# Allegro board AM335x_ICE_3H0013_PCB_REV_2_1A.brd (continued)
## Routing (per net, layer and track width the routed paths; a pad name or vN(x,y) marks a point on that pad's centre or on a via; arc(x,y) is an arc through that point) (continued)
DDR_D13: length 24.9
  TOP w0.121: v1(44.97,46.05) U14.L3 ; U15.A2 v1(59.7,51.02)
  LYR4 w0.127: v1(59.7,51.02) 59.31,51.41 55.82,51.41 55.71,51.3 55.71,50.76 55.6,50.65 55.44,50.65 55.33,50.76 55.33,51.3 55.22,51.41 55.06,51.41 54.95,51.3 54.95,50.76 54.84,50.65 54.68,50.65 54.57,50.76 54.57,51.3 54.46,51.41 54.3,51.41 54.19,51.3 54.19,50.76 54.08,50.65 53.92,50.65 53.81,50.76 53.81,51.3 53.7,51.41 53.43,51.41 53.2,51.18 53.2,50.73 53.05,50.58 51.79,50.58 51.55,50.82 51.55,51.16 51.3,51.41 50.84,51.41 50.59,51.16 50.59,49.85 50.27,49.53 48.25,49.53 47.65,48.93 47.65,47.77 47.12,47.24 45.61,47.24 45.38,47.01 45.38,46.46 v1(44.97,46.05)
DDR_D14: length 25.1
  TOP w0.121: U14.L4 v1(44.17,46.05) ; v1(62.99,50.8) 63.35,50.45 U15.A7
  LYR4 w0.127: v1(62.99,50.8) 61.62,52.17 49.58,52.17 46.25,48.84 44.81,48.84 44.56,48.6 44.56,48.29 44.32,48.04 44.01,48.04 43.78,47.81 43.78,46.44 v1(44.17,46.05)
DDR_D15: length 25.1
  TOP w0.121: U14.M1 v1(46.57,46.85) ; U15.B8 v1(64.9,49.25)
  LYR4 w0.127: v1(64.9,49.25) 64.9,50.6 64.52,50.98 63.92,50.98 63.64,50.7 63.64,50.48 63.36,50.21 62.77,50.21 62.36,50.62 60.07,50.62 59.85,50.41 58.92,50.41 58.34,50.98 56.56,50.98 56.39,50.81 56.39,50.33 56.27,50.21 55.35,50.21 55.35,50.2 51.19,50.2 51,50.01 51,49.27 50.84,49.11 48.35,49.11 48,48.76 48,47.4 47.45,46.85 v1(46.57,46.85)
DDR_DQM0: length 24.8
  TOP w0.121: U14.M2 v1(45.77,46.85) ; U15.E7 v1(63.06,47.25)
  LYR3 w0.127: v1(63.06,47.25) 63.06,46.58 62.6,46.11 62.07,46.11 61.57,45.61 61.57,45.6 61.34,45.37 61.02,45.37 60.78,45.6 60.78,46.07 59.6,47.26 59.14,47.26 58.91,47.49 58.91,47.94 58.41,48.44 58.41,48.91 58.18,49.14 57.8,49.14 57.62,48.96 57.62,48.41 57.52,48.31 50.62,48.31 50.16,48.77 47.64,48.77 46.91,48.04 45.61,48.04 45.38,47.81 45.38,47.32 45.77,46.93 v1(45.77,46.85)
DDR_DQM1: length 25
  TOP w0.121: v1(61.06,48.32) 60.78,48.05 U15.D3 ; U14.J2 45.77,44.45 46.4,44.45 46.86,44.9 v1(47.22,44.9)
  LYR4 w0.127: v1(61.06,48.32) 60.87,48.14 59.12,48.14 58.52,47.54 57.36,47.54 57.26,47.65 56.06,47.65 55.95,47.53 55.95,47.28 55.84,47.17 55.68,47.17 55.57,47.28 55.57,47.53 55.46,47.65 55.3,47.65 55.19,47.53 55.19,47.28 55.07,47.17 54.92,47.17 54.8,47.28 54.8,47.53 54.69,47.65 54.54,47.65 54.41,47.52 54.41,46.83 54.3,46.71 54.15,46.71 54.03,46.83 54.03,47.54 53.93,47.65 53.77,47.65 53.65,47.52 53.65,46.83 53.54,46.71 53.38,46.71 53.27,46.83 53.27,47.54 53.17,47.65 53.01,47.65 52.89,47.52 52.89,46.83 52.78,46.71 52.62,46.71 52.52,46.82 52.52,47.53 52.41,47.65 51.93,47.65 51.7,47.42 51.7,46.33 51.44,46.07 49.32,46.07 48.15,44.9 v1(47.22,44.9)
DDR_DQS0: length 25
  TOP w0.102: U14.P1 v1(46.57,48.45) ; v1(61.18,46.36) 60.8,45.98 60.57,45.98 60.5,46.05 U15.F3
  LYR3 w0.102: v1(61.18,46.36) 61.26,46.43 61.26,47.12 61.08,47.3 60.96,47.3 60.57,46.91 60.41,46.91 60.29,47.04 60.29,47.18 60.68,47.57 60.68,47.7 59.99,48.39 59.2,48.39 58.62,48.97 58.62,49.47 58.44,49.65 57.67,49.65 56.83,48.8 56.19,48.8 55.89,49.1 55.89,49.6 55.79,49.71 55.49,49.71 55.37,49.59 55.37,49.09 55.09,48.8 54.59,48.8 54.29,49.1 54.29,49.53 54.17,49.65 53.94,49.65 53.83,49.53 53.83,49.1 53.53,48.8 53.11,48.8 52.81,49.1 52.81,49.53 52.69,49.65 52.52,49.65 52.4,49.53 52.4,49.1 52.11,48.8 50.82,48.8 50.36,49.27 46.9,49.27 46.42,48.8 46.42,48.6 v1(46.57,48.45)
DDR_DQS1: length 25
  TOP w0.102: U15.C7 63.7,49.18 63.55,49.33 63.2,49.33 63.06,49.2 v1(63.06,48.85)
  TOP w0.121: U14.L1 v1(46.57,46.05)
  LYR4 w0.102: v1(46.57,46.05) 47.94,46.05 48.74,46.85 48.74,48.08 48.89,48.24 51.15,48.24 51.43,48.52 51.81,48.9 51.81,49.25 51.97,49.4 52.52,49.4 52.65,49.27 52.65,48.86 52.94,48.57 53.54,48.57 53.82,48.85 53.82,49.31 53.91,49.4 54.31,49.4 54.4,49.31 54.4,48.91 54.68,48.63 55.3,48.63 55.58,48.91 55.58,49.28 55.68,49.38 55.95,49.38 56.08,49.38 56.16,49.29 56.16,48.92 56.44,48.63 57,48.63 57.31,48.94 57.31,49.46 57.48,49.63 59.14,49.63 59.15,49.63 60.44,49.63 60.84,50.03 61.5,50.03 62.27,49.27 62.64,49.27 v1(63.06,48.85)
DDR_DQSN0: length 25
  TOP w0.102: U15.G3 60.53,45.67 61.08,45.67 v1(61.18,45.77) ; U14.P2 v1(45.77,48.45)
  LYR3 w0.102: v1(45.77,48.45) 46.02,48.7 46.02,48.82 46.77,49.58 50.48,49.58 50.95,49.11 51.98,49.11 52.1,49.23 52.1,49.66 52.4,49.95 52.82,49.95 53.11,49.66 53.11,49.23 53.23,49.11 53.4,49.11 53.52,49.23 53.52,49.66 53.82,49.95 54.3,49.95 54.59,49.66 54.59,49.23 54.71,49.11 54.96,49.11 55.07,49.22 55.07,49.71 55.37,50.01 55.91,50.01 56.2,49.72 56.2,49.23 56.32,49.11 56.7,49.11 57.54,49.95 58.57,49.95 58.93,49.59 58.93,49.41 58.92,49.41 58.92,49.09 59.32,48.69 60.12,48.69 61.56,47.25 61.56,46.15 v1(61.18,45.77)
DDR_DQSN1: length 25
  TOP w0.102: U15.B7 63.69,49.64 62.43,49.64 v1(62.42,49.65) ; U14.L2 v1(45.77,46.05)
  LYR4 w0.102: v1(45.77,46.05) 46.15,46.43 46.73,46.43 46.81,46.35 47.81,46.35 48.44,46.98 48.44,48.21 48.77,48.54 51.02,48.54 51.31,48.83 51.51,49.03 51.51,49.37 51.84,49.71 52.65,49.71 52.96,49.4 52.96,48.99 53.07,48.88 53.41,48.88 53.51,48.98 53.51,49.44 53.79,49.71 54.44,49.71 54.71,49.44 54.71,49.04 54.8,48.94 55.17,48.94 55.27,49.04 55.27,49.41 55.55,49.68 55.82,49.68 56.2,49.68 56.47,49.42 56.47,49.17 56.47,49.04 56.57,48.94 56.88,48.94 57.01,49.07 57.01,49.59 57.36,49.94 59.27,49.94 60.31,49.94 60.71,50.34 61.63,50.34 62.2,49.76 62.31,49.76 v1(62.42,49.65)
DDR_ODT: length 32.2
  TOP w0.121: U15.K1 58.13,43.25 v1(58.09,43.29) ; v1(46.57,42.05) 46.83,41.79 47.22,41.79 47.46,42.04 47.46,42.25 47.26,42.45 U14.G1
  LYR4 w0.127: v1(46.57,42.05) 46.61,42.09 47.16,42.09 47.28,41.97 47.28,41.58 47.39,41.47 47.55,41.47 47.66,41.58 47.66,41.99 47.76,42.09 47.92,42.09 48.04,41.97 48.04,41.58 48.15,41.47 48.31,41.47 48.42,41.58 48.42,41.99 48.52,42.09 50.19,42.09 50.49,42.39 52.21,42.39 52.27,42.39 52.35,42.31 52.35,41.88 52.49,41.75 52.68,41.75 52.8,41.86 52.8,42.84 52.91,42.96 53.06,42.96 53.15,42.87 53.15,42.56 53.24,42.47 53.43,42.47 53.53,42.57 53.53,42.99 53.64,43.1 53.98,43.1 54.11,43.24 54.11,43.64 54.23,43.75 54.38,43.75 54.51,43.63 54.51,43.08 54.61,42.98 54.76,42.98 54.89,43.11 54.89,43.65 54.99,43.75 55.15,43.75 55.27,43.63 55.27,43.07 55.36,42.98 55.55,42.98 55.65,43.08 55.65,43.65 55.75,43.75 55.91,43.75 56.03,43.63 56.03,43.07 56.11,42.99 56.33,42.99 56.41,43.08 56.41,43.65 56.51,43.75 56.67,43.75 56.79,43.63 56.79,43.08 56.88,42.99 57.28,42.99 57.58,43.29 v1(58.09,43.29)
  BOTTOM w0.121: v1(58.09,43.29) 58.25,43.13 58.3,43.13 58.75,42.68 58.75,38.96 58.19,38.41 RP3.2
DDR_RASN: length 31.7
  TOP w0.121: U14.G4 v1(44.17,42.05) ; U15.J3 61.43,44.05 v1(61.52,44.15)
  LYR4 w0.127: v1(44.17,42.05) 43.78,42.44 43.78,44.41 44.01,44.64 44.3,44.64 44.56,44.38 44.56,43.5 44.81,43.26 45.13,43.26 45.49,43.61 49.34,43.61 49.86,44.14 52.96,44.14 53.73,44.92 57.23,44.92 57.37,45.06 59.04,45.06 59.33,45.35 60.5,45.35 60.65,45.19 60.65,44.69 60.65,44.68 60.65,44.54 60.78,44.41 61.26,44.41 v1(61.52,44.15)
  BOTTOM w0.121: v1(61.52,44.15) 61.42,44.05 59.08,44.05 58.04,45.09 55.83,45.09 55.32,44.58
DDR_RESETN: length 33.8
  TOP w0.121: U15.T2 v1(59.3,38.05) 53.42,38.05 R59.2 ; U14.G2 v1(45.77,42.05)
  LYR3 w0.127: v1(59.3,38.05) 58.93,38.42 58.4,38.42 57.83,37.84 56.83,37.84 55.18,39.49 54.7,39.49 54.59,39.6 54.59,40.12 54.48,40.23 54.32,40.23 54.21,40.12 54.21,39.6 54.1,39.49 53.94,39.49 53.83,39.6 53.83,40.12 53.72,40.23 53.56,40.23 53.45,40.12 53.45,39.6 53.34,39.49 53.18,39.49 53.07,39.6 53.07,40.12 52.95,40.23 52.8,40.23 52.69,40.12 52.69,39.6 52.57,39.49 52.42,39.49 52.3,39.6 52.3,40.12 52.19,40.23 52.03,40.23 51.92,40.12 51.92,39.6 51.81,39.49 51.65,39.49 51.54,39.6 51.54,40.12 51.43,40.23 51.27,40.23 51.16,40.12 51.16,39.6 51.05,39.49 50.89,39.49 50.78,39.6 50.78,40.12 50.67,40.23 50.51,40.23 50.4,40.12 50.4,39.6 50.29,39.49 50.13,39.49 50.02,39.6 50.02,40.12 49.91,40.23 49.75,40.23 49.64,40.12 49.64,39.6 49.53,39.49 49.13,39.49 49.02,39.6 49.02,40.16 48.91,40.27 48.71,40.27 48.43,39.99 47.97,39.99 47.92,40.04 46.42,40.04 46.18,40.29 46.18,40.6 45.93,40.84 45.62,40.84 45.38,41.09 45.38,41.41 45.61,41.64 45.61,41.64 45.77,41.8 v1(45.77,42.05)
DDR_VREF: length 43.2
  TOP w0.254: U15.M8 v1(64.9,41.25)
  TOP w0.305: U14.J4 v1(44.17,43.65)
  TOP w0.381: U15.H1 57.89,44.85 v1(56.52,46.23) 52.83,46.23 TP21.1
  BOTTOM w0.254: U29.6 67.33,36.94 67.18,37.08 C188.1
  BOTTOM w0.381: C188.1 67.18,39.37 67.69,39.88 67.69,40.77 67.18,41.27 66.67,41.27
  BOTTOM w0.508: 66.67,41.27 64.93,41.27 v1(64.9,41.25) 64.75,41.4 64.75,41.43 C167.1 64.27,42.2 64.03,42.44 64.03,44.7 62.79,45.94 62.42,45.94 61.42,46.94 58.93,46.94 58.56,47.31 57.2,47.31 56.52,46.63 v1(56.52,46.23) 53.98,46.23 51.31,43.56 C159.1 46.61,44.32 44.7,44.32 44.17,43.79 v1(44.17,43.65)
DDR_VTP: length 4.7
  TOP w0.121: v1(44.97,43.65) U14.J3
  BOTTOM w0.121: v1(44.97,43.65) 45.36,43.26 45.36,41.91 45.61,41.66 47.11,41.66 R185.2
DDR_VTT_EN: length 79.7
  TOP w0.121: v1(33.77,41.25) U14.F16 ; 70.48,32.64 70.13,32.99 v1(69.85,32.99) 69.23,32.99 R62.2 68.75,33.47 68.75,34.31 68.79,34.35 68.79,34.74 68.75,34.78 68.75,36.41 v1(68.07,37.08)
  LYR3 w0.127: v1(29.35,26.12) 29.38,26.12 30.77,24.73 37.72,24.73 37.92,24.53 42.68,24.53 44.93,22.29 53.98,22.29 55.12,21.15 v1(55.12,20.95) ; v1(33.77,41.25) 33.6,41.08 33.52,41.08 32.07,39.64 30.19,39.64 29.21,38.66 v1(29.21,38.25)
  LYR4 w0.127: v1(29.35,26.12) 29.33,26.13 29.33,29.72 29.11,29.94 29.11,31.34 28.53,31.92 28.53,32.52 29.01,32.99 29.01,37.81 29.21,38.01 v1(29.21,38.25) ; v1(69.85,32.99) 69.85,30.7 67.83,28.69 64.03,28.69 63.63,28.28 60,28.28 58.62,26.9 55.27,26.9 54.32,25.95 54.32,23.41 55.12,22.61 v1(55.12,20.95)
  BOTTOM w0.121: U29.7 67.83,36.84 v1(68.07,37.08)
DDR_WEN: length 31.2
  TOP w0.121: U15.L3 61.54,42.45 62.36,41.62 v1(62.36,41.6) ; U14.B2 v1(45.77,38.05)
  LYR4 w0.127: v1(45.77,38.05) 46.28,37.54 46.29,37.54 46.82,37.01 50.2,37.01 50.57,37.38 53.62,37.38 53.69,37.31 58.01,37.31 59.14,38.44 59.47,38.44 59.71,38.2 61.06,38.2 61.18,38.09 61.5,38.09 61.98,38.56 61.98,40.32 62.24,40.58 62.24,40.9 62.54,41.2 63.13,41.2 63.29,41.36 63.29,41.64 63.16,41.77 62.53,41.77 v1(62.36,41.6)
  BOTTOM w0.121: v1(62.36,41.6) 62.25,41.48 62.25,40.62 61.99,40.37 61.99,39.53 62.34,39.18 62.34,37.6 62.76,37.18 RP2.2
DRAIN0: length 80.3
  TOP w0.121: J14.19 74.44,27.16 74.44,51.47 73.43,52.47 v1(73.43,55.81) ; D15.1 v1(77.35,81.57)
  LYR3 w0.127: v1(77.35,81.57) 76.77,80.99 76.77,77.24 77.57,76.44 77.57,60.52 73.41,56.36 73.41,55.84 v1(73.43,55.81)
  LYR4 w0.127: J14.19 74.87,24.83 71.41,24.83 68.99,22.42 60.4,22.42 v1(59.07,21.08)
  BOTTOM w0.121: U31.3 58.55,21.57 59.04,21.08 v1(59.07,21.08)
DRAIN1: length 83.3
  TOP w0.121: J14.20 71.82,27.24 71.82,32.47 71.7,32.58 71.7,34.47 71.18,34.99 71.18,38.03 69.26,39.95 69.26,51.99 69.85,52.58 v1(69.85,53.09) ; D14.1 v1(74.93,81.57)
  LYR3 w0.127: v1(74.93,81.57) 75.68,80.83 75.68,77.1 77.06,75.72 77.06,61.43 72.87,57.24 72.6,57.24 72.17,56.82 72.17,53.55 71.2,52.58 70.36,52.58 v1(69.85,53.09)
  LYR4 w0.127: J14.20 73.24,25.74 71.7,25.74 68.73,22.77 58.25,22.77 v1(57.28,23.75)
  BOTTOM w0.121: U31.4 v1(57.28,23.75)
DRAIN2: length 87.2
  TOP w0.121: D12.1 v1(72.52,81.57) ; v1(73.91,52.58) 74.68,51.81 74.68,29.59 75.82,28.46 J14.21
  LYR3 w0.127: v1(73.91,52.58) 72.43,54.06 72.43,56.71 72.7,56.98 72.97,56.98 77.32,61.33 77.32,76.33 75.93,77.72 75.93,82 75.02,82.91 73.86,82.91 v1(72.52,81.57)
  LYR4 w0.127: J14.21 74.42,26.92 72.49,26.92 68.59,23.03 58.64,23.03 57.49,24.17 56.43,24.17 v1(56.01,23.75)
  BOTTOM w0.121: U31.5 v1(56.01,23.75)
DRAIN3: length 82.5
  TOP w0.121: D10.1 v1(70.11,81.57) ; J14.22 72.06,29.54 72.06,32.57 71.95,32.69 71.95,34.73 71.43,35.25 71.43,52.78 v1(71.12,53.09)
  LYR3 w0.127: v1(70.11,81.57) 71.1,80.57 71.1,80.13 73.27,77.97 73.27,77.06 75.12,75.21 75.12,62.55 72.86,60.29 71.67,60.29 71.41,60.03 71.41,58.67 70.83,58.09 70.83,53.38 v1(71.12,53.09)
  LYR4 w0.127: J14.22 71.51,26.56 70.27,26.56 67.68,23.96 62.54,23.96 61.91,23.33 59.15,23.33 58.05,24.42 55.41,24.42 v1(54.74,23.75)
  BOTTOM w0.121: U31.6 v1(54.74,23.75)
DRAIN4: length 74.1
  TOP w0.121: J14.23 77.25,32.29 77.25,52.23 77.72,52.7 77.72,76.87 v1(77.35,77.25) D9.1
  LYR4 w0.127: v1(54.74,25.78) 55.68,24.84 58.27,24.84 58.81,24.3 65.54,24.3 66.7,25.46 68.63,25.46 72.51,29.34 74.3,29.34 J14.23
  BOTTOM w0.121: U31.11 v1(54.74,25.78)
DRAIN5: length 73.5
  TOP w0.121: v1(71.25,53.85) 71.68,53.42 71.68,35.51 72.2,34.99 72.2,32.99 72.4,32.79 72.4,31.74 J14.24 ; D8.1 v1(74.93,77.25)
  LYR3 w0.127: v1(74.93,77.25) 76.45,75.74 76.45,74.11 76.07,73.73 76.07,64.01 76.29,63.79 76.29,61.02 76.01,60.74 75.74,60.74 71.89,56.89 71.89,54.49 v1(71.25,53.85)
  LYR4 w0.127: v1(56.01,25.78) 56.68,25.11 59.74,25.11 61.05,26.42 61.05,26.79 61.78,27.52 63.05,27.52 63.76,26.8 65.02,26.8 65.4,27.18 69.6,27.18 J14.24
  BOTTOM w0.121: U31.12 v1(56.01,25.78)
DRAIN6: length 73.6
  TOP w0.121: J14.25 76.87,34.45 76.87,53.05 v1(76.77,53.15) 76.78,53.15 77.48,53.85 77.48,75.69 76.96,76.2 73.55,76.2 73.15,76.6 73.15,76.62 v1(72.52,77.25) D7.1
  LYR4 w0.127: J14.25 74.42,32 73.07,32 72.33,31.26 72.33,31.06 68.83,27.56 65.15,27.56 64.9,27.31 63.63,27.31 63.16,27.77 61.18,27.77 58.76,25.36 57.73,25.36 57.32,25.78 v1(57.28,25.78)
  BOTTOM w0.121: U31.13 v1(57.28,25.78)
DRAIN7: length 83
  TOP w0.121: D6.1 v1(70.11,77.25) ; v1(71.37,54.99) 72,54.36 72,35.69 72.44,35.25 72.44,34.24 J14.26
  LYR3 w0.127: v1(71.37,54.99) 71.37,58.28 71.67,58.57 71.67,59.86 71.84,60.03 72.96,60.03 75.37,62.44 75.37,73.85 75.94,74.42 75.94,75.71 75.46,76.2 75.18,76.2 74.2,77.18 74.2,78.9 70.19,82.91 69.8,82.91 69.53,82.63 69.53,81.55 70.47,80.61 70.47,77.61 v1(70.11,77.25)
  LYR4 w0.127: v1(58.55,25.78) 60.79,28.03 63.73,28.03 64.14,28.43 69.34,28.43 72.07,31.17 72.07,32.19 J14.26
  BOTTOM w0.121: U31.14 v1(58.55,25.78)
EMU2_GPIO0_19: length 118.1
  TOP w0.121: U14.A15 34.59,37.27 34.59,35.87 34.24,35.53 34.24,33.69 34.34,33.59 34.34,33.45 34.53,33.26 34.53,31.88 v1(35.62,30.8) ; v1(71.12,62.43) 73.16,64.47 R35.2
  LYR3 w0.127: v1(71.12,62.43) 71.75,63.06 71.75,65.65 72.39,66.29 72.39,67.65 72.27,67.77 72.27,70.15 72.27,70.15 72.27,73.67 71.6,74.33 70,74.33 69.13,75.2 69.13,75.48 67.56,77.05 67.56,84.2 67.02,84.75 67.02,90.49 v1(68.74,92.21)
  LYR4 w0.127: v1(35.62,30.8) 36.51,30.8 37.08,30.23 45.3,30.23 46.01,29.52 52.64,29.52 52.87,29.29 59.63,29.29 59.87,29.53 60.47,29.53 60.49,29.5 65.07,29.5 65.34,29.78 65.34,29.95 68.96,33.57 69.41,33.57 70.37,34.52 70.37,38.65 70.7,38.99 70.7,55.12 71.5,55.92 71.5,61.47 71.12,61.85 v1(71.12,62.43)
  BOTTOM w0.121: v1(68.74,92.21) 70.37,92.21 70.64,92.49 R106.2 72.3,93.23 72.81,92.72 Q2.2
EMU2R: length 2.9
  TOP w0.121: R35.1 v1(76.61,64.47)
  BOTTOM w0.121: v1(76.61,64.47) J15.17
EMU3_GPIO0_20: length 106.8
  TOP w0.121: R26.1 68.56,65.92 v1(67.05,65.92) ; v1(35.37,39.65) U14.D14
  LYR4 w0.127: v1(68.74,90.18) 67.02,88.46 67.02,83.6 68.07,82.55 68.07,77.34 69.13,76.29 72.56,76.29 73.31,75.53 73.31,73.91 71.81,72.41 70.99,72.41 67.05,68.47 v1(67.05,65.92) 67.05,65.11 68.39,63.78 68.39,57.89 68.13,57.64 68.13,38.77 62.85,33.49 60.53,33.49 59.54,32.5 57.41,32.5 57.23,32.68 47.97,32.68 47.41,33.24 44.95,33.24 44.02,34.17 42.21,34.17 37.93,38.45 36.81,38.45 36.57,38.69 36.57,39.01 36.33,39.25 35.94,39.25 35.54,39.65 v1(35.37,39.65)
  BOTTOM w0.121: Q3.5 71.53,90.31 R108.2 69.63,90.18 v1(68.74,90.18)
EMU3R: length 3.9
  TOP w0.121: R26.2 70.39,65.74 v1(71.28,64.85)
  BOTTOM w0.121: v1(71.28,64.85) 70.9,64.47 J15.18
EMU4: length 157.4
  TOP w0.121: R36.2 72.66,63.2 71.44,61.98 v1(70.1,61.98) ; v1(35.46,31.71) 35.39,31.71 34.78,32.31 34.78,33.36 34.64,33.51 34.64,34.76 35,35.12 35,36.88 U14.A14
  LYR3 w0.127: v1(9.65,40.51) 9.65,38.69 12.88,35.46 12.88,33.77 14.51,32.14 15.29,32.14 17.04,30.39 18.72,30.39 19.97,29.14 21.6,29.14 22.35,29.88 25.68,29.88 26.25,29.31 28.41,29.31 28.66,29.07 28.68,29.07 28.68,29.07 31.61,29.07 34.03,31.49 35.24,31.49 v1(35.46,31.71)
  LYR4 w0.127: J3.10 3.55,82.55 3.55,71.38 4.52,70.41 4.52,65.56 5.7,64.38 5.7,62.63 7.74,60.59 7.74,56.3 8.55,55.5 8.55,48.64 9.25,47.94 9.25,40.91 v1(9.65,40.51) ; v1(35.46,31.71) 35.57,31.71 35.85,31.99 36.39,31.99 37.54,30.84 39.3,30.84 39.62,31.15 41.65,31.15 42.32,30.48 46.25,30.48 46.84,29.88 52.63,29.88 52.97,29.54 59.52,29.54 59.87,29.88 60.84,29.88 61.4,30.44 64.89,30.44 68.8,34.35 68.8,34.74 68.75,34.79 68.75,36.08 70.11,37.45 70.11,38.77 70.45,39.11 70.45,55.97 70.57,56.1 70.57,61.51 v1(70.1,61.98)
EMU4R: length 4.7
  TOP w0.121: R36.1 v1(75.47,61.93)
  BOTTOM w0.121: J15.19 76.11,63.2 76.49,62.82 76.49,62.44 75.98,61.93 v1(75.47,61.93)
EMU_RSTN: length 9.4
  TOP w0.121: R20.1 76.12,70.82 77.09,69.85 77.09,66.85 v1(76.61,66.38) 75.98,65.74 C13.1
  BOTTOM w0.121: J15.15 76.36,65.74 76.61,65.99 v1(76.61,66.38)
ENZ_KALDO_1P8V: length 6
  TOP w0.121: R65.1 45.63,33.87 45.63,34.46 44.17,35.92 44.17,38.06 43.78,38.45 U14.B4
ETH0_CLKIN: length 40.1
  TOP w0.121: v1(52.2,74.04) 51.92,74.32 U3.34 ; v1(66.55,61.21) 75.56,61.21 76.96,59.82 76.96,56.64 R42.2
  LYR4 w0.127: v1(66.55,61.21) 65.91,61.21 65.41,61.72 62.18,61.72 59.94,63.96 59.94,71.12 58.01,73.05 57.05,73.05 56.07,74.04 v1(52.2,74.04)
ETH1_CLKIN: length 61.3
  TOP w0.121: U2.34 33.3,74.32 32.79,73.81 32.79,72.64 v1(33.66,71.77)
  BOTTOM w0.121: v1(33.66,71.77) 34.27,71.17 34.27,69.83 35.6,68.5 35.6,67.14 36.58,66.16 36.58,65.45 36.71,65.32 37.04,64.99 42.83,64.99 43.03,65.19 44.1,65.19 44.5,64.79 46.35,64.79 46.49,64.93 46.61,64.93 46.85,65.17 46.85,67.4 48.24,68.79 51.38,68.79 52.03,69.45 52.28,69.45 52.3,69.43 52.31,69.43 52.96,68.79 55.65,68.79 56.24,69.38 61.45,69.38 63.43,67.4 64.58,67.4 65.02,66.95 65.02,63.5 65.66,62.87 66.19,62.87 68.12,60.93 73.59,60.93 74.07,60.45 74.07,60.42 R154.2
F_ADBUS0: length 4.1
  TOP w0.121: U18.16 12.64,25.21 12.83,25.02 v1(12.83,24.64)
  BOTTOM w0.121: v1(12.83,24.64) 12.83,23.11 13.08,22.86 R209.2
F_ADBUS1: length 10.9
  TOP w0.121: v1(18.54,30.99) 18.03,30.99 13.27,26.22 U18.17
  BOTTOM w0.121: v1(18.54,30.99) R192.2
F_ADBUS2: length 12.1
  TOP w0.121: U18.18 13.77,25.96 18.29,30.48 18.8,30.48 19.05,30.73 19.05,31.5 v1(18.54,32)
  BOTTOM w0.121: R190.2 v1(18.54,32)
F_ADBUS3: length 9.1
  TOP w0.121: v1(18.54,29.97) 14.27,25.7 U18.19
  BOTTOM w0.121: R194.2 v1(18.54,29.97)
F_ADBUS4: length 7.7
  TOP w0.121: v1(18.54,28.96) 15.27,25.68 U18.21
  BOTTOM w0.121: R201.2 v1(18.54,28.96)
F_ADBUS5: length 4.7
  TOP w0.121: v1(18.54,26.92) 17.77,26.15 U18.26
  BOTTOM w0.121: v1(18.54,26.92) R203.2
F_ADBUS6: length 6.3
  TOP w0.121: U18.23 16.27,25.67 v1(18.54,27.94)
  BOTTOM w0.121: R202.2 v1(18.54,27.94)
F_ADBUS7: length 4.1
  TOP w0.121: U18.30 19.77,24.23 19.56,24.43 19.15,24.43 18.54,25.04 v1(18.54,25.91)
  BOTTOM w0.121: v1(18.54,25.91) R204.2
F_EECS: length 23
  TOP w0.121: v1(12.45,35.31) 12.45,35.61 12.65,35.81 13.51,35.81 13.77,35.56 U18.63
  BOTTOM w0.121: R210.1 9.02,23.37 8.89,23.24 U33.5 7.37,23.24 6.86,23.75 6.86,25.65 6.27,26.24 6.27,32.3 7.11,33.15 11.18,33.15 11.81,33.78 11.81,34.67 11.81,34.67 11.81,34.93 12.18,35.3 12.44,35.3 v1(12.45,35.31)
F_EEDATA: length 20.8
  TOP w0.121: U18.61 14.77,35.52 v1(14.48,35.81)
  BOTTOM w0.121: U33.3 5.56,24.66 5.08,25.15 R207.1 5.08,26.16 6.02,27.1 6.02,32.44 6.99,33.4 11.02,33.4 11.4,33.78 11.4,35.03 12.19,35.81 v1(14.48,35.81)
F_EEDOUT: length 6
  BOTTOM w0.121: R207.2 6.1,25.15 6.48,24.77 6.48,22.61 6.16,22.29 U33.1 3.87,22.29 R211.1
F_EESK: length 18.6
  TOP w0.121: v1(13.97,33.27) 14.27,33.57 U18.62
  BOTTOM w0.121: U33.4 8.15,24.79 8.64,25.27 R206.1 8.64,26.29 7.66,27.27 7.02,27.27 6.68,27.61 6.68,32.33 7.24,32.89 13.08,32.89 13.46,33.27 v1(13.97,33.27)
FET_NOE: length 118.4
  TOP w0.121: U4.7 69.54,74.1 69.54,72.97 69.22,72.64 R11.2 66.93,72.64 v1(66.67,72.39) 66.17,71.88 66.17,70.53 66.67,70.02 68.54,70.02 68.91,69.65 U4.1 ; v1(23.41,41) 23.41,37.88 25.03,36.26 30.49,36.26 31.34,37.1 31.34,38.02 31.36,38.04 U14.C18
  LYR3 w0.127: v1(23.41,41) 23.24,41 22.09,42.15 22.09,44.59 21.08,45.59 19.81,45.59 18.29,47.12 18.29,50.93 19.56,52.2 19.56,52.32 v1(19.58,52.32)
  LYR4 w0.127: v1(31.03,72.6) 29.63,74 29.63,78.4 29.84,78.61 32.98,78.61 34.16,79.79 44.15,79.79 48.5,75.44 49.72,75.44 50.39,76.11 56.84,76.11 57,76.27 61.47,76.27 v1(61.47,76.27)
  BOTTOM w0.121: v1(19.58,52.32) 19.58,51.63 20.09,51.12 23.59,51.12 25.04,52.56 25.04,57.94 26.4,59.31 26.4,64.4 30.04,68.05 30.21,68.21 30.21,70.61 31.03,71.43 v1(31.03,72.6) ; v1(66.67,72.39) 65.98,73.09 65.98,74.04 65.6,74.42 63.75,74.42 63.25,74.93 63.25,75.95 62.74,76.45 61.65,76.45 v1(61.47,76.27)
FT_REF: length 2.1
  TOP w0.121: U18.6 10.43,30.21 v1(10.16,30.48)
  BOTTOM w0.121: R193.2 v1(10.16,30.48)
FT_RESETN: length 2.4
  TOP w0.121: U18.14 10.41,26.21 10.2,26 v1(10.2,25.65)
  BOTTOM w0.121: R205.1 v1(10.2,25.65)
FT_SRESET: length 103.2
  TOP w0.121: v1(64.39,72.39) 64.14,72.14 U10.2
  LYR3 w0.127: v1(21.04,27.26) 21.42,27.26 21.61,27.46 24.2,27.46 24.66,27.92 34.8,27.92 35.31,28.42 36.29,28.42 37.33,27.38 38.61,27.38 39.39,26.59 42.85,26.59 v1(44.21,25.23) ; v1(64.39,72.39) 65.06,71.72 65.06,71.05 65.34,70.78 66,70.78 67,69.78 67,66.87 66.63,66.5 66.63,63.59 65.7,62.66 65.7,60.14 62.98,57.42 62.98,53.64 63.41,53.2 63.41,52.92 65.41,50.93 66.29,50.93 67.73,49.49 67.73,45.88 67.43,45.57 67.43,38.47 65.98,37.03 65.98,36.72 63.02,33.75 59.74,33.75 59.44,33.45 58.81,33.45 58.53,33.18 58.53,32.69 58.19,32.36 57.27,32.36 57.26,32.35 53.66,32.35 v1(53.47,32.16)
  BOTTOM w0.121: R137.2 63.75,71.75 v1(64.39,72.39) 64.39,71.12 64.14,70.87 R141.1 ; v1(53.47,32.16) 53.15,31.84 53.15,30.59 51.57,29.01 51.57,25.65 51.06,25.14 48.3,25.14 48.15,24.99 47.26,24.99 47.18,24.92 44.52,24.92 v1(44.21,25.23) ; v1(21.04,27.26) 20.91,27.26 20.57,26.92 R203.1
GPIO2-5: length 49.3
  TOP w0.121: U5.1 49.02,72.47 R21.1 49.53,74.17 v1(49.78,73.91) ; v1(42.57,50.05) U14.T6
  LYR4 w0.127: v1(42.57,50.05) 43.95,51.44 43.95,51.63 45.98,53.66 47.62,53.66 48.45,52.83 53.42,52.83 54.06,53.47 58.05,53.47 58.8,54.23 58.8,58.4 57.87,59.33 57.87,60.75 57.89,60.76 57.89,67.56 57.6,67.85 57.6,68.27 58.33,69 58.33,70.66 57.23,71.75 51.53,71.75 50.84,72.45 50.84,72.86 v1(49.78,73.91)
GPIO2_12: length 73.2
  TOP w0.121: U37.5 v1(56.7,55.32) ; v1(44.97,50.05) U14.T3 ; v1(20.37,85.43) U1.C3
  LYR3 w0.127: v1(44.97,50.05) 42.53,52.49 42.22,52.49 41.57,53.13 41.57,56.26 36.25,61.58 30.41,61.58 29.06,62.92 29.06,70.43 29.75,71.11 29.75,81.3 30.31,81.87 30.31,82.77 28.54,84.55 28.54,84.93 v1(27.81,85.65)
  BOTTOM w0.121: v1(20.37,85.43) 20.76,85.82 21.52,85.82 22.3,85.04 27.38,85.04 27.77,85.43 27.77,85.65 v1(27.81,85.65) ; v1(44.97,50.05) 45.28,50.36 45.28,51.64 45.97,52.33 46.2,52.33 48.61,54.74 52.11,54.74 52.24,54.6 53.43,54.6 53.82,54.99 54.48,54.99 54.86,54.61 55.99,54.61 v1(56.7,55.32)
GPIO2_13: length 72.3
  TOP w0.121: U1.D4 v1(21.17,87.03) ; v1(44.17,50.05) U14.T4 ; U37.3 v1(55.4,55.27)
  LYR3 w0.127: v1(27.81,84.87) 27.8,84.87 27.8,84.82 30.06,82.55 30.06,81.97 29.5,81.41 29.5,71.22 28.81,70.53 28.81,62.69 30.29,61.22 36.14,61.22 41.16,56.19 41.16,53.06 v1(44.17,50.05)
  BOTTOM w0.121: v1(21.17,87.03) 21.56,87.42 27.11,87.42 28.56,85.97 28.56,85.54 27.8,84.78 27.8,84.85 v1(27.81,84.87) ; v1(55.4,55.27) 53.75,55.27 53.33,54.85 52.35,54.85 52.21,54.99 48.5,54.99 46.19,52.68 46,52.68 44.96,51.63 44.96,50.84 v1(44.17,50.05)
GPIO3_18: length 129.6
  TOP w0.121: U14.B12 v1(36.97,38.05)
  LYR3 w0.127: v1(36.97,38.05) 37.16,38.05 37.55,38.44 37.93,38.44 38.61,37.77 38.61,33.53 36.52,31.44 36.52,31.13 ; 36.52,31.13 35.88,31.13 35.79,31.22 35.44,31.22 34.58,30.36 34.58,29.97 33.43,28.82 28.58,28.82 28.55,28.82 28.49,28.88 19.63,28.88 18.96,29.55 15.59,29.55 15.2,29.94 15.2,30.48 13,32.68 12.96,32.68 12.04,33.59 12.04,33.8 v1(10.54,35.31) ; 36.52,31.13 36.53,31.13 38.38,29.29 40.66,29.29 40.73,29.36 41.89,29.36 42.59,29.36 44.46,27.49 44.46,26.41 44.9,25.97 45.36,25.97 45.89,26.5 46.81,26.5 46.86,26.45 59.74,26.45 60.24,25.95 60.24,21.66 59.19,20.61 59.19,18.31 v1(59.15,18.31)
  LYR4 w0.127: v1(10.54,35.31) 10.67,35.43 10.67,55.38 9.22,56.83 9.22,62.87 6.83,65.26 6.83,81.81 J3.9
  BOTTOM w0.121: R244.1 59.05,18.41 v1(59.15,18.31) 59.19,18.31 U35.26
GPIO3_19: length 81.6
  TOP w0.121: v1(36.17,38.85) U14.C13
  LYR4 w0.127: v1(25.28,50.28) 26.61,50.28 27.36,49.53 29.42,49.53 29.43,49.54 29.83,49.54 30.42,48.95 31.06,48.95 31.81,48.2 31.81,42.88 32.68,42.01 32.68,40.18 33.61,39.25 35.54,39.25 35.93,38.85 v1(36.17,38.85)
  BOTTOM w0.121: 9.53,53.11 11.19,54.77 16.71,54.77 19.17,52.31 19.17,51.7 19.99,50.87 24.71,50.87 25.14,50.45 25.14,50.42 v1(25.28,50.28) ; 9.53,53.11 8.38,54.25 8.38,54.74 6.47,56.65 4.41,56.65 2.22,58.84 2.22,60.24 4.53,62.55 4.53,66.25 7.3,69.02 7.3,83.89 J3.11 ; 9.53,53.11 U28.7
GPIO3_20: length 82.5
  TOP w0.121: v1(36.17,39.65) U14.D13
  LYR3 w0.127: v1(19.56,53.09) 19.98,52.67 19.98,52.52 20,52.5 20,52.15 19.98,52.13 19.98,51.6 18.85,50.47 18.85,47.12 19.99,45.97 21.21,45.97 22.39,44.79 22.39,44.26 23.88,42.77 23.88,41.06 25.41,39.53 26.91,39.53 28.86,37.58 31.94,37.58 33.61,39.25 35.54,39.25 35.93,39.65 v1(36.17,39.65)
  BOTTOM w0.121: v1(19.56,53.09) 15.74,56.9 4.99,56.9 2.8,59.1 2.8,60.39 2.86,60.45 2.86,60.48 4.78,62.4 4.78,66.12 7.54,68.88 7.54,86.18 J3.13
GPMC_A0: length 37.3
  TOP w0.121: v1(18.41,68.45) 18.88,68.92 20.07,68.92 20.75,68.25 20.75,67.48 20.6,67.34 20.03,67.34 19.93,67.25 19.93,66.95 20.03,66.86 20.6,66.86 20.75,66.72 20.75,64.48 19.34,63.08 14.37,63.08 13.27,64.17 J4.1 ; v1(21.3,83.29) 21.43,83.29 U1.E1
  LYR4 w0.127: v1(18.41,68.45) 19.54,68.45 20.69,69.61 20.69,81.49 21.3,82.11 v1(21.3,83.29)
  BOTTOM w0.121: U26.2 18.53,68.57 v1(18.41,68.45)
GPMC_A1: length 37.5
  TOP w0.121: v1(17.65,68.45) 18.1,68 19.01,68 19.44,67.58 19.44,66.28 19.58,66.14 20.24,66.14 20.38,66 20.38,65.8 20.24,65.66 19.58,65.66 19.44,65.52 19.44,64.02 18.86,63.44 15.11,63.44 14.29,64.27 14.29,66.8 J4.3 ; v1(21.17,83.83) U1.D1
  LYR4 w0.127: v1(21.17,83.83) 20.88,83.55 20.88,82.23 20.31,81.65 20.31,81.46 20.31,69.99 19.29,68.98 18.18,68.98 v1(17.65,68.45)
  BOTTOM w0.121: v1(17.65,68.45) 18.17,68.97 U26.3
GPMC_A2: length 36.8
  TOP w0.121: v1(20.37,83.83) U1.C1 ; J4.5 13.85,70.36 14.65,69.56 14.65,64.49 14.93,64.21 18.19,64.21 18.68,64.7 18.68,66.59 17.24,68.03 17.24,68.78 17.51,69.05 18,69.05 v1(18.41,69.47)
  LYR4 w0.127: v1(20.37,83.83) 20.37,82.71 19.92,82.26 19.92,71.43 19.72,71.23 19.18,71.23 19.03,71.08 19.03,70.87 19.18,70.72 19.79,70.72 19.9,70.61 19.9,70.2 19.78,70.08 18.54,70.08 18.41,69.96 v1(18.41,69.47)
  BOTTOM w0.121: U26.5 19.02,69.77 18.71,69.47 v1(18.41,69.47)
GPMC_A3: length 36.2
  TOP w0.121: U1.A1 18.62,83.68 17.62,83.68 v1(17.61,83.69) ; J4.7 15.01,71.16 15.01,65.19 15.48,64.73 17.29,64.73 17.76,65.2 17.76,66.6 16.75,67.61 16.75,68.86 17.36,69.47 v1(17.65,69.47)
  LYR4 w0.127: v1(17.65,69.47) 16.61,70.51 16.61,76.56 16.7,76.65 16.7,76.65 16.94,76.9 16.95,76.9 17.4,77.35 17.4,83.48 v1(17.61,83.69)
  BOTTOM w0.121: v1(17.65,69.47) 18.16,69.98 18.67,69.98 18.86,70.17 U26.6
GPMC_A4: length 37.1
  TOP w0.121: v1(19.57,83.83) U1.B1 ; J4.9 13.9,74.81 13.9,74.04 15.37,72.56 15.37,66.09 15.65,65.81 16.14,65.81 16.39,66.06 16.39,69.16 17.81,70.59 18.01,70.59 v1(18.54,71.12)
  LYR4 w0.127: v1(18.54,71.12) 18.52,71.1 18.52,70.6 18.26,70.35 17.43,70.35 17.13,70.65 17.13,71.55 17.35,71.78 19.35,71.78 19.54,71.97 19.54,83.81 v1(19.57,83.83)
  BOTTOM w0.121: v1(18.54,71.12) 18.69,70.97 U26.8
GPMC_A5: length 37.2
  TOP w0.121: v1(17.68,71.15) 17.35,71.15 14.53,73.97 14.53,78.49 14.64,78.6 14.64,78.61 15.68,79.65 15.68,80.9 15.43,81.15 15.17,81.15 14.92,80.9 14.92,79.98 14.33,79.39 13.43,79.39 13.27,79.23 J4.11 ; v1(21.17,84.63) U1.D2
  LYR3 w0.127: v1(21.17,84.63) 20.77,84.23 20.77,82.38 18.84,80.46 18.84,75.67 19.72,74.8 19.72,71.08 19.32,70.68 18.14,70.68 v1(17.68,71.15)
  BOTTOM w0.121: U26.9 19,71.37 18.81,71.56 18.09,71.56 v1(17.68,71.15)
GPMC_A6: length 37.6
  TOP w0.121: v1(18.41,72.26) 18,71.85 17.17,71.85 15.01,74.01 15.01,78.46 16.1,79.56 16.1,81.76 15.43,82.44 14.88,82.44 14.51,82.06 14.51,80.81 14.22,80.52 J4.13 ; v1(20.37,84.63) U1.C2
  LYR3 w0.127: v1(20.37,84.63) 19.98,84.24 19.98,82.57 18.46,81.05 18.46,75.52 19.22,74.76 19.22,72.15 18.67,71.6 17.32,71.6 17.19,71.74 17.19,72.52 17.39,72.73 17.95,72.73 v1(18.41,72.26)
  BOTTOM w0.121: v1(18.41,72.26) 18.51,72.17 U26.11
GPMC_A7: length 37
  TOP w0.121: J4.15 13.27,84.14 13.49,84.35 14.19,84.35 16.47,82.08 16.47,79.41 15.5,78.45 15.5,74.02 17.26,72.26 v1(17.65,72.26) ; v1(18.77,84.63) U1.A2
  LYR4 w0.127: v1(17.65,72.26) 17.75,72.26 18.28,72.8 18.64,72.8 19.03,73.19 19.03,83.95 19.18,84.11 19.18,86.03 19.06,86.14 18.39,86.14 18.2,85.95 18.2,85.2 v1(18.77,84.63)
  BOTTOM w0.121: U26.12 18.7,72.57 18.59,72.68 18.07,72.68 v1(17.65,72.26)
GPMC_A8: length 37.7
  TOP w0.121: J4.17 13.92,86.25 14.46,86.25 15.03,85.68 15.03,84.06 17.06,82.02 17.06,77.49 16.67,77.09 16.67,76.7 16.55,76.58 16.55,73.6 17.32,72.82 17.96,72.82 v1(18.41,73.28) ; U1.B5 v1(19.57,87.83)
  LYR3 w0.127: v1(18.41,73.28) 18.83,73.7 18.83,74.59 18.06,75.36 18.06,81.73 19.18,82.85 19.18,86.09 19.3,86.22 20.59,86.22 20.76,86.39 20.76,87.2 20.53,87.43 19.98,87.43 v1(19.57,87.83)
  BOTTOM w0.121: U26.13 19.9,73.01 18.85,73.01 18.58,73.28 v1(18.41,73.28)
GPMC_A9: length 37.3
  TOP w0.121: J4.19 15.48,85.93 15.48,84.41 17.53,82.36 17.53,76.31 17.24,76.01 17.24,73.7 v1(17.65,73.28) ; U1.A5 v1(18.77,87.83)
  LYR4 w0.127: v1(17.65,73.28) 17.23,73.7 17.23,74.84 17.86,75.47 17.86,83.19 18.03,83.35 18.03,83.87 17.68,84.21 17.18,84.21 16.86,84.53 16.86,86.92 17.32,87.38 18.32,87.38 v1(18.77,87.83)
  BOTTOM w0.121: v1(17.65,73.28) 18.1,73.72 18.65,73.72 19,73.37 U26.14
GPMC_A10: length 20.3
  TOP w0.121: U1.C5 v1(20.37,87.83)
  LYR3 w0.127: v1(18.41,74.17) 18,73.75 17.18,73.75 16.8,74.13 16.8,74.87 17.62,75.68 17.62,82.15 18.32,82.85 18.32,85.86 19.16,86.71 19.16,87.98 19.41,88.23 19.98,88.23 v1(20.37,87.83)
  BOTTOM w0.121: v1(18.41,74.17) 18.42,74.17 U26.16
GPMC_A11: length 20.4
  TOP w0.121: U1.D5 v1(21.17,87.83)
  LYR4 w0.127: v1(17.65,74.17) 17.65,74.18 18.64,75.17 18.64,84.12 17.65,85.12 17.65,86.08 18.2,86.64 20.57,86.64 20.76,86.83 20.76,87.43 v1(21.17,87.83)
  BOTTOM w0.121: v1(17.65,74.17) 18.1,74.62 19.77,74.62 19.79,74.6 19.91,74.6 U26.17
GPMC_A12: length 20.6
  TOP w0.121: U1.B6 v1(19.57,88.63)
  LYR4 w0.127: v1(16.03,76.33) 15.99,76.33 15.64,76.68 15.64,86.67 18.16,89.19 19.02,89.19 v1(19.57,88.63)
  BOTTOM w0.121: U26.19 17.38,75.37 17.13,75.63 16.85,75.63 16.14,76.33 v1(16.03,76.33)
GPMC_A13: length 20
  TOP w0.121: U1.A6 v1(18.77,88.63)
  LYR3 w0.127: v1(18.77,88.63) 18.22,88.09 18.22,87.7 17.09,86.56 17.09,86.13 17.24,85.99 17.72,85.99 17.86,85.84 17.86,85.63 17.72,85.48 17.24,85.48 17.09,85.33 17.09,85.12 17.24,84.97 17.72,84.97 17.86,84.82 17.86,84.61 17.72,84.46 17.24,84.46 17.09,84.31 17.09,77.71 v1(16.25,76.88)
  BOTTOM w0.121: U26.20 17.51,75.77 17.26,76.02 16.98,76.02 16.25,76.75 16.25,76.87 v1(16.25,76.88)
GPMC_A14: length 20.2
  TOP w0.121: U1.C6 20.41,88.59 v1(20.36,88.59)
  LYR3 w0.127: v1(16.6,78.8) 16.6,87.37 18.27,89.04 19.91,89.04 v1(20.36,88.59)
  BOTTOM w0.121: v1(16.6,78.8) 16.06,78.8 15.65,78.39 15.65,77.92 15.96,77.61 16.05,77.61 16.37,77.29 16.46,77.29 16.46,77.28 17.69,77.28 18.4,76.57 U26.22
GPMC_A15: length 20.6
  TOP w0.121: U1.D6 v1(21.17,88.63)
  LYR3 w0.127: v1(21.17,88.63) 20.39,89.42 18.08,89.42 15.89,87.23 15.89,78.3 v1(16.07,78.12)
  BOTTOM w0.121: U26.23 18.57,76.97 17.87,77.66 16.52,77.66 v1(16.07,78.12)
GPMC_AD0: length 113.5
  TOP w0.121: U14.U7 41.79,50.87 41.79,52.38 41.59,52.57 41.59,54.56 41.45,54.71 41.45,55.86 39.39,57.92 38.34,57.92 36.14,60.12 36.14,60.12 35.85,60.42 34.52,60.42 34.52,60.41 29.48,60.41 27.71,62.18 27.71,63.4 25.61,65.5 25.61,73.9 24.55,74.95 24.55,75.1 25.12,75.67 25.12,75.82 25.01,75.93 24.87,75.93 24.3,75.36 24.15,75.36 24.04,75.47 24.04,75.62 24.61,76.18 24.61,76.33 24.5,76.44 24.35,76.44 23.79,75.87 23.64,75.87 23.46,76.05 23.46,76.18 23.75,76.47 23.75,76.77 23.27,77.25 21.57,77.25 v1(21.53,77.22) 21.53,77.31 22.07,77.85 25.71,77.85 27.18,79.32 27.18,84.45 25.46,86.17 22.23,86.17 21.99,85.94 21.99,85.41 U1.E2
  LYR4 w0.127: v1(21.53,77.22) 21.53,76.88 21.93,76.48 24.67,76.48 24.92,76.24 24.92,65.7 23.99,64.77 20.06,64.77 19.17,63.87 19.17,62.93 18.46,62.22 12.81,62.22 11.96,63.07 11.96,64.05 J4.2
  BOTTOM w0.121: v1(21.53,77.22) 21.62,77.13 21.62,71.95 21.63,71.94 21.63,71.6 21.62,71.6 21.62,69.55 21.63,69.54 21.63,69.2 21.62,69.2 21.62,68.35 21.63,68.34 21.63,68 21.62,68 21.62,66.25 22.12,65.75 24,65.75 24.36,66.11 24.36,68.45 24.49,68.57 U26.47
GPMC_AD1: length 113
  TOP w0.121: U1.H2 25.16,84.64 v1(25.17,84.64) 25.56,84.25 25.56,83.46 25.4,83.29 22.49,83.29 22.31,83.11 22.31,82.82 22.5,82.63 24.92,82.63 25.25,82.3 25.25,81.39 25.95,80.69 25.95,79.23 25.3,78.57 22.99,78.57 22.83,78.73 22.82,78.73 22.72,78.83 22.18,78.83 21.59,78.24 v1(21.32,78.24) 21.32,78.23 21.12,78.02 21.12,76.82 21.32,76.61 22.36,76.61 22.54,76.44 22.69,76.44 22.98,76.73 23.13,76.73 23.24,76.63 23.24,76.48 22.94,76.18 22.94,76.03 25.17,73.81 25.17,68.58 25.06,68.47 24.53,68.47 24.43,68.37 24.43,68.22 24.53,68.11 25.06,68.11 25.17,68.01 25.17,67.86 25.06,67.75 24.53,67.75 24.43,67.64 24.43,67.49 24.53,67.39 25.06,67.39 25.17,67.28 25.17,67.13 25.06,67.03 24.53,67.03 24.43,66.92 24.43,66.77 24.56,66.64 25.08,66.64 25.17,66.56 25.17,65.26 27.35,63.08 27.35,62.03 29.33,60.05 34.67,60.05 34.67,60.05 35.6,60.05 38.1,57.56 39.24,57.56 41.03,55.77 41.03,54.62 41.37,54.27 U14.V7
  BOTTOM w0.121: U26.46 24.38,68.97 24.37,68.95 24.08,68.95 23.97,68.85 23.97,66.62 23.76,66.41 22.31,66.41 21.94,66.78 21.94,77.03 21.95,77.04 21.95,77.39 21.95,77.39 21.95,77.61 v1(21.32,78.24) 20.34,78.24 19.36,79.22 15.7,79.22 15.27,78.8 15.27,77.12 15.56,76.84 15.56,63.91 14.92,63.27 10.32,63.27 9.29,64.29 9.29,66.38 J4.4
GPMC_AD2: length 110.5
  TOP w0.121: v1(40.97,49.25) U14.R8 ; v1(22.77,85.43) U1.E3
  LYR3 w0.127: v1(21.54,78.78) 21.75,78.57 21.75,77.92 24.74,74.94 24.74,71.26 24.63,71.15 24.21,71.15 24.1,71.04 24.1,70.88 24.21,70.77 24.63,70.77 24.74,70.66 24.74,68.1 24.63,67.99 24.24,67.99 24.12,67.88 24.12,67.72 24.24,67.61 24.63,67.61 24.74,67.49 24.74,67.34 24.63,67.22 24.24,67.22 24.12,67.11 24.12,66.96 24.24,66.84 24.63,66.84 24.74,66.73 24.74,65.44 25.31,64.86 25.31,64.34 25.69,63.96 25.69,62.81 29.57,58.93 32.31,58.93 33.05,58.19 35.55,58.19 38.3,55.45 38.3,52.06 39.64,50.72 39.64,49.86 39.85,49.65 40.57,49.65 v1(40.97,49.25)
  LYR4 w0.127: v1(22.77,85.43) 22.84,85.5 22.84,86.49 22.71,86.61 22.32,86.61 22.12,86.42 22.12,80.41 22.78,79.75 22.78,79.52 22.65,79.39 22.65,78.91 23.48,78.08 23.48,77.64 23.13,77.3 22.15,77.3 21.9,77.55 21.9,78.42 v1(21.54,78.78)
  BOTTOM w0.121: J4.6 11.8,69.29 11.8,63.93 12.03,63.7 14.61,63.7 15.2,64.29 15.2,76.58 14.91,76.87 14.91,79.25 15.25,79.58 19.98,79.58 20.79,78.78 v1(21.54,78.78) 22.25,78.07 22.25,77.51 22.25,77.51 22.25,76.92 22.24,76.91 22.24,67.24 22.59,66.9 23.51,66.9 23.65,67.04 23.65,69.64 23.8,69.79 25.51,69.79 U26.44
GPMC_AD3: length 109
  TOP w0.121: U1.H3 v1(25.17,85.43) 25.64,85.43 26.62,84.45 26.62,84.21 26.52,84.11 26.03,84.11 25.93,84 25.93,83.72 26.03,83.62 26.69,83.62 26.79,83.51 26.79,83.24 26.69,83.14 25.86,83.14 25.75,83.03 25.75,82.75 25.86,82.64 26.65,82.64 26.82,82.47 26.82,81.8 26.72,81.7 26.54,81.7 26.35,81.51 26.35,79.09 25.47,78.21 22.84,78.21 22.68,78.37 22.67,78.37 22.63,78.41 v1(22.55,78.41) ; v1(40.97,50.05) U14.T8
  LYR3 w0.127: v1(40.97,50.05) 40.97,50.63 38.98,52.63 38.98,54.12 39.52,54.66 39.52,55.68 35.5,59.7 29.88,59.7 26.45,63.12 26.45,64.27 26.32,64.41 26.32,66.37 25.69,67 25.69,70.46 25.8,70.57 26.46,70.57 26.57,70.68 26.57,70.84 26.46,70.95 25.8,70.95 25.69,71.07 25.69,71.22 25.8,71.34 26.46,71.34 26.57,71.45 26.57,71.6 26.46,71.72 25.8,71.72 25.69,71.83 25.69,71.99 25.8,72.1 26.46,72.1 26.55,72.19 26.55,72.27 26.57,72.29 26.57,72.37 26.46,72.48 25.8,72.48 25.69,72.59 25.69,72.75 25.8,72.86 26.46,72.86 26.57,72.97 26.57,73.13 26.46,73.24 25.8,73.24 25.69,73.35 25.69,75.27 v1(22.55,78.41)
  BOTTOM w0.121: U26.43 23.61,70.17 23.32,69.89 23.32,67.43 23.16,67.27 22.73,67.27 22.55,67.45 22.55,76.79 22.55,76.79 22.55,78.41 v1(22.55,78.41) 22.5,78.41 21.72,79.19 21.23,79.19 20.48,79.95 15.04,79.95 14.53,79.44 14.53,76.74 14.69,76.58 14.69,74.19 14.4,73.9 14.4,73.89 14.29,73.77 14.29,73.22 14.43,73.08 14.76,73.08 14.84,73 14.84,72.8 14.76,72.72 14.38,72.72 14.29,72.63 14.29,72.45 14.38,72.35 14.76,72.35 14.84,72.27 14.84,72.1 14.71,71.97 14.17,71.97 14.06,71.86 14.06,71.71 14.17,71.61 14.71,71.61 14.82,71.5 14.82,71.35 14.71,71.25 14.28,71.25 14.18,71.14 14.18,70.99 14.28,70.88 14.71,70.88 14.82,70.78 14.82,70.63 14.71,70.52 14.35,70.52 14.29,70.46 14.29,69.12 14,68.83 12.74,68.83 12.13,69.45 12.13,72.53 11.76,72.9 J4.8
GPMC_AD4: length 103.1
  TOP w0.121: U1.H4 v1(25.17,87.03) ; U14.U8 40.97,50.85 40.97,53.86 40.86,53.98 40.86,54.42 40.53,54.75 40.53,55.76 39.09,57.19 37.95,57.19 35.45,59.69 34.82,59.69 34.82,59.69 29.18,59.69 26.99,61.88 26.99,62.89 24.06,65.82 24.06,68.72 24.16,68.83 24.37,68.83 24.38,68.84 24.58,68.84 24.78,69.04 24.78,69.88 24.67,69.99 24.24,69.99 24.13,70.09 24.13,70.24 24.24,70.35 24.67,70.35 24.78,70.45 24.78,70.6 24.67,70.71 24.24,70.71 24.13,70.82 24.13,70.97 24.24,71.07 24.67,71.07 24.78,71.18 24.78,71.33 24.67,71.43 24.24,71.43 24.13,71.54 24.13,71.69 24.24,71.8 24.67,71.8 24.78,71.9 24.78,72.05 24.67,72.16 24.24,72.16 24.13,72.26 24.13,72.41 24.24,72.52 24.67,72.52 24.78,72.63 24.78,73.38 22,76.16 21.26,76.16 20.75,76.67 20.75,78.86 21.08,79.19 21.72,79.19 21.72,79.19 22.87,79.19 22.97,79.09 23.06,79.09 v1(23.13,79.02)
  LYR3 w0.127: v1(25.17,87.03) 25.17,86.49 26.79,84.87 26.79,83.9 27.29,83.39 27.29,81.52 27.56,81.25 27.56,80.59 25.99,79.02 v1(23.13,79.02)
  BOTTOM w0.121: U26.41 25.52,70.98 24.56,70.98 24.47,70.89 24.47,70.61 24.35,70.48 24.04,70.48 23.94,70.59 23.94,70.88 23.81,71 23.6,71 23.47,70.87 23.47,70.46 23.36,70.35 23.01,70.35 22.86,70.51 22.86,78.06 23.38,78.58 23.38,78.72 23.1,78.99 v1(23.13,79.02) 23.06,79.09 22.28,79.09 22.24,79.09 21.03,80.31 16.16,80.31 16.04,80.44 16.04,81.52 15.93,81.62 15.68,81.62 15.57,81.52 15.57,80.39 15.49,80.31 15.18,80.31 15.07,80.41 15.07,81.48 14.93,81.62 14.74,81.62 14.61,81.5 14.61,80.29 14.16,79.84 14.16,79.33 13.89,79.06 12.28,79.06 11.9,78.67 11.9,77.25 12.42,76.72 13.91,76.72 14.33,76.3 14.33,74.81 13.56,74.04 12.13,74.04 J4.10
GPMC_AD5: length 97.7
  TOP w0.121: U1.E4 v1(22.77,87.03) ; v1(22.3,79.63) 20.78,79.63 20.39,79.25 20.39,75.9 21.11,75.19 21.34,75.19 21.8,75.65 21.95,75.65 22.06,75.54 22.06,75.39 21.56,74.89 21.56,74.74 21.66,74.63 21.81,74.63 22.32,75.13 22.47,75.13 22.57,75.03 22.57,74.88 22.07,74.38 22.07,74.23 22.18,74.12 22.33,74.12 22.83,74.62 22.98,74.62 23.08,74.52 23.08,74.37 22.58,73.86 22.58,73.71 22.69,73.61 22.84,73.61 23.34,74.11 23.49,74.11 23.6,74 23.6,73.85 23.09,73.35 23.09,73.2 23.67,72.62 23.67,65.61 23.99,65.3 23.99,65.15 23.76,64.92 23.76,64.77 23.87,64.66 24.02,64.66 24.25,64.89 24.4,64.89 24.5,64.78 24.5,64.63 24.27,64.4 24.27,64.25 24.38,64.15 24.53,64.15 24.76,64.38 24.91,64.38 26.62,62.66 26.62,61.73 29.6,58.76 35.87,58.76 37.8,56.83 38.1,56.83 38.94,56.83 40.15,55.62 40.15,54.61 40.51,54.25 40.51,53.82 40.75,53.58 40.75,51.74 40.57,51.56 U14.V8
  LYR4 w0.127: v1(22.77,87.03) 22,87.03 21.73,86.76 21.73,80.21 v1(22.3,79.63)
  BOTTOM w0.121: U26.40 25.51,71.35 24.6,71.35 24.55,71.3 23.43,71.3 23.16,71.58 23.16,77.93 23.73,78.5 23.73,79.01 23.28,79.46 22.48,79.46 v1(22.3,79.63) 21.2,80.74 17.78,80.74 15.95,82.58 14.72,82.58 14.47,82.82 14.47,84.16 14.16,84.48 12.32,84.48 11.9,84.06 11.9,79.47 11.69,79.27 9.59,79.27 9.26,78.94 9.26,76.76 9.47,76.55 10.48,76.55 10.73,76.81 J4.12
GPMC_AD6: length 101.4
  TOP w0.121: U1.H5 v1(25.17,87.83) ; v1(40.17,49.25) U14.R9
  LYR3 w0.127: v1(25.17,87.83) 24.76,87.43 24.76,86.46 25.62,85.61 25.62,84.33 26.91,83.04 26.91,81.36 27.18,81.1 27.18,80.75 25.91,79.47 v1(23.86,79.47) 23.85,79.48 23,79.48 22.73,79.21 21.27,79.21 20.91,78.85 20.91,77.25 23.57,74.59 23.57,70.42 23.46,70.31 23.14,70.31 23.03,70.2 23.03,70.04 23.14,69.93 23.46,69.93 23.57,69.82 23.57,69.66 23.46,69.55 23.14,69.55 23.03,69.44 23.03,69.28 23.14,69.17 23.46,69.17 23.57,69.06 23.57,68.9 23.46,68.79 23.14,68.79 23.03,68.68 23.03,68.52 23.14,68.41 23.46,68.41 23.57,68.29 23.57,68.14 23.46,68.03 23.14,68.03 23.03,67.91 23.03,67.76 23.14,67.64 23.46,67.64 23.57,67.53 23.57,67.37 23.46,67.26 23.14,67.26 23.03,67.15 23.03,66.99 23.14,66.88 23.46,66.88 23.57,66.77 23.57,66.61 23.46,66.5 23.14,66.5 23.03,66.39 23.03,66.23 23.14,66.12 23.46,66.12 23.57,66.01 23.57,64.48 24,64.05 25.07,64.05 25.31,63.8 25.31,63.45 25.07,63.21 25.07,62.89 29.42,58.54 30.33,58.54 31.78,58.54 32.51,57.81 35.05,57.81 37.43,55.43 37.43,52.22 39.12,50.52 39.12,49.81 39.68,49.25 v1(40.17,49.25)
  BOTTOM w0.121: U26.38 25.52,72.17 24.59,72.17 24.51,72.09 24.51,71.69 24.42,71.6 23.57,71.6 23.46,71.71 23.46,71.99 23.56,72.09 24.1,72.09 24.22,72.21 24.22,72.42 24.11,72.53 23.63,72.53 23.47,72.69 23.47,77.82 24.03,78.37 24.03,79.3 23.86,79.47 v1(23.86,79.47) 23.86,79.55 23.79,79.48 23.72,79.48 23.6,79.59 23.58,79.59 23.36,79.81 22.92,79.81 21.62,81.12 18.3,81.12 15.17,84.25 15.17,86.77 14.87,87.06 12.19,87.06 11.75,86.62 11.75,84.67 11.38,84.3 9.42,84.3 9.19,84.08 9.19,80.92 9.6,80.52 J4.14
GPMC_AD7: length 104.5
  TOP w0.121: U1.E5 v1(22.77,87.83) ; v1(40.17,50.05) U14.T9
  LYR3 w0.127: v1(40.17,50.05) 40.17,50.85 38.63,52.4 38.63,54.31 39.14,54.82 39.14,55.35 35.87,58.61 33.49,58.61 32.79,59.31 29.72,59.31 26.07,62.97 26.07,64.12 25.82,64.37 25.82,65.88 25.24,66.47 25.24,75.06 22.13,78.16 22.13,78.59 22.38,78.83 22.73,78.83 22.96,78.6 26.11,78.6 27.94,80.43 27.94,81.49 v1(27.71,81.72)
  LYR4 w0.127: J4.16 12.25,84.58 13.69,84.58 14.6,85.49 14.6,88.98 15.93,90.31 24.72,90.31 28.3,86.73 28.3,83.84 27.71,83.25 v1(27.71,81.72) 27.65,81.72 27.39,81.98 27.39,87.13 25.35,89.18 23.53,89.18 23.16,88.81 23.16,88.47 22.77,88.08 v1(22.77,87.83)
  BOTTOM w0.121: U26.37 29.01,72.57 29.74,73.3 29.74,80.63 28.69,81.67 27.76,81.67 v1(27.71,81.72)
GPMC_AD8: length 94.1
  TOP w0.121: v1(23.57,84.63) U1.F2 ; v1(23.1,80.28) 22.94,80.43 22.52,80.43 22.41,80.33 22.41,80.2 22.31,80.09 22.15,80.09 22.05,80.2 22.05,80.33 21.94,80.43 21.7,80.43 21.6,80.34 21.6,80.11 21.5,80 21.35,80 21.24,80.11 21.24,80.32 21.12,80.43 20.87,80.43 20.03,79.59 20.03,75.68 20.46,75.25 20.46,75.09 20.03,74.66 20.03,74.51 20.14,74.4 20.29,74.4 20.73,74.84 20.87,74.84 20.97,74.74 20.97,74.58 20.54,74.15 20.54,74 20.65,73.89 20.8,73.89 21.24,74.33 21.38,74.33 22.02,73.69 22.02,73.54 21.56,73.08 21.56,72.89 21.66,72.78 21.78,72.78 22.28,73.29 22.43,73.29 22.53,73.18 22.53,73.03 22.07,72.57 22.07,72.38 22.18,72.27 22.29,72.27 22.79,72.77 22.94,72.77 23.12,72.6 23.12,72.45 22.8,72.14 22.8,71.95 22.93,71.83 23.09,71.83 23.25,71.68 23.25,64.68 25.88,62.06 25.88,61.26 29.12,58.01 35.45,58.01 37.41,56.05 38.44,56.05 39.37,55.12 39.37,53.77 39.76,53.37 39.76,51.84 39.35,51.44 39.35,50.83 U14.U10
  LYR4 w0.127: v1(23.57,84.63) 22.96,84.03 22.96,83.33 23.07,83.22 23.5,83.22 23.6,83.12 23.6,81.98 24.36,81.22 24.36,80.89 24.27,80.8 23.26,80.8 23.1,80.64 v1(23.1,80.28)
  BOTTOM w0.121: J4.18 9.59,86.74 9.59,88.98 10.13,89.51 11.74,89.51 11.86,89.63 15.17,89.63 15.56,89.24 15.56,84.4 18.41,81.55 21.83,81.55 v1(23.1,80.28) 23.32,80.28 23.7,79.9 24.09,79.9 24.33,79.66 24.33,78.25 23.81,77.73 23.81,73.37 24.21,72.97 U26.36
GPMC_AD9: length 104.8
  TOP w0.121: v1(24.37,84.63) U1.G2 ; v1(38.57,50.05) U14.T10
  LYR3 w0.127: v1(38.57,50.05) 38.18,49.66 36.81,49.66 36.58,49.89 36.58,50.76 35.78,51.55 35.78,54.9 34.01,56.67 29.67,56.67 20.53,65.81 20.53,75.46 19.76,76.23 19.76,79.32 22.09,81.65 24.93,81.65 25.31,82.03 25.57,82.03 v1(25.73,82.19) 25.7,82.19 25.14,82.76 22.64,82.76 21.72,83.69 21.72,88.76 20.23,90.25 20.23,94.17 19.86,94.54 15.62,94.54 15.32,94.24 12.07,94.24 11.8,93.97 11.8,89.2 J4.20
  LYR4 w0.127: v1(24.37,84.63) 24.78,85.04 24.78,85.74 24.95,85.91 25.52,85.91 25.81,85.61 25.81,85.37 25.56,85.12 25.56,84.88 25.81,84.63 25.81,84.4 25.66,84.25 24.99,84.25 24.76,84.02 24.76,83.69 24.99,83.46 25.64,83.46 25.77,83.33 25.77,83.17 25.65,83.05 24.49,83.05 24.37,82.93 24.37,82.75 24.51,82.61 25.61,82.61 25.73,82.49 v1(25.73,82.19)
  BOTTOM w0.121: v1(25.73,82.19) 26.08,82.19 27.31,80.97 27.46,80.97 29.44,78.99 29.44,73.96 28.75,73.28 26.44,73.28 26.43,73.29 26.35,73.29 26.27,73.37 U26.35
GPMC_AD10: length 101.5
  TOP w0.121: v1(23.57,85.43) U1.F3 ; v1(37.77,50.05) U14.T11
  LYR3 w0.127: v1(37.77,50.05) 37.77,51.05 37.05,51.77 37.05,55.18 34.79,57.43 31.98,57.43 31.25,58.16 30.18,58.16 30.18,58.16 29.51,58.16 29.51,58.16 29.26,58.16 22.38,65.04 22.38,71.45 22.5,71.56 22.99,71.56 23.11,71.68 23.11,71.83 22.99,71.95 22.5,71.95 22.38,72.06 22.38,72.21 22.5,72.33 22.99,72.33 23.11,72.44 23.11,72.6 22.99,72.71 22.5,72.71 22.38,72.82 22.38,72.98 22.5,73.09 22.99,73.09 23.11,73.2 23.11,73.36 22.99,73.47 22.5,73.47 22.38,73.58 22.38,74.93 20.52,76.79 20.52,79.01 21.6,80.08 22.71,80.08 22.93,79.86 23.46,79.86 23.5,79.89 24.05,79.89 24.89,80.73 26.57,80.73 v1(26.76,80.92) 26.53,81.16 26.53,81.86 26.53,81.86 26.53,82.53 26.53,82.53 26.53,82.86 25.94,83.44 23.36,83.44 22.96,83.84 22.96,85.06 23.16,85.27 23.16,85.62 22.96,85.83 22.77,85.83 22.63,85.97 22.63,86.36 22.87,86.6 23.38,86.6 23.57,86.41 v1(23.57,85.43)
  LYR4 w0.127: J4.22 11.76,91.71 24.25,91.71 25.26,90.7 28.68,87.28 28.68,83.68 28.13,83.13 28.13,81.55 27.84,81.25 27.09,81.25 v1(26.76,80.92)
  BOTTOM w0.121: U26.33 26.54,74.17 26.6,74.23 27.62,74.23 28.03,73.82 28.64,73.82 29.13,74.32 29.13,78.87 27.5,80.5 27.14,80.5 26.72,80.92 v1(26.76,80.92)
GPMC_AD11: length 97
  TOP w0.121: v1(23.87,80.31) 23.87,80.19 24.25,79.81 24.53,79.81 24.7,79.98 24.7,80.36 24.26,80.8 20.72,80.8 19.66,79.73 19.66,74.25 20.12,73.78 20.12,73.56 19.76,73.2 19.76,73.02 19.86,72.92 20,72.92 20.44,73.35 20.59,73.35 20.69,73.24 20.69,73.09 20.27,72.67 20.27,72.51 20.38,72.4 20.57,72.4 20.98,72.81 21.11,72.81 21.98,71.94 21.98,71.8 21.59,71.4 21.59,71.27 21.7,71.17 21.85,71.17 22.28,71.6 22.44,71.6 22.77,71.28 22.77,64.65 25.51,61.9 25.51,60.9 29.55,56.86 30.14,56.86 30.28,57.01 35.03,57.01 36.82,55.22 36.82,54.3 37.21,53.92 37.21,51.68 37.03,51.5 37.03,50.79 U14.U12 ; v1(24.37,85.43) U1.G3
  LYR4 w0.127: v1(23.87,80.31) 24.17,80.31 24.27,80.21 24.27,79.72 24.37,79.62 24.66,79.62 24.77,79.73 24.77,81.34 23.98,82.14 23.98,85.04 v1(24.37,85.43)
  BOTTOM w0.121: U26.32 24.61,74.57 24.51,74.48 24.51,73.5 24.39,73.39 24.25,73.39 24.11,73.52 24.11,77.6 24.64,78.12 24.64,80.21 24.86,80.44 24.86,80.72 24.67,80.92 24.09,80.92 23.87,80.7 v1(23.87,80.31) 23.31,80.88 23.09,80.88 22.91,81.06 21.99,81.98 18.73,81.98 18.53,82.19 18.53,82.34 18.88,82.69 18.88,82.84 18.78,82.95 18.63,82.95 18.27,82.59 18.12,82.59 18.01,82.7 18.01,82.85 18.37,83.2 18.37,83.35 18.26,83.46 18.11,83.46 17.76,83.1 17.61,83.1 16.64,84.07 16.64,84.22 16.99,84.58 16.99,84.73 16.88,84.83 16.73,84.83 16.38,84.48 16.23,84.48 16,84.71 16,90.86 14.92,91.95 12.48,91.95 11.97,92.45 11.5,92.45 J4.24
GPMC_AD12: length 98.4
  TOP w0.121: v1(36.97,50.05) U14.T12 ; U1.F4 v1(23.57,87.03)
  LYR3 w0.127: J4.26 10.88,95.76 12.02,94.62 13.98,94.62 14.6,95.24 20.07,95.24 21.17,94.14 21.17,89.97 21.2,89.95 21.2,89.88 22.18,88.9 22.18,84.06 23.1,83.14 25.38,83.14 26.15,82.37 26.15,82.02 25.74,81.61 v1(25.71,81.61) 25.71,81.58 25.68,81.58 25.68,81.58 25.29,81.19 24.31,81.19 23.86,80.74 21.71,80.74 20.14,79.16 20.14,76.6 21.73,75.01 21.73,74.76 21.62,74.65 21.05,74.65 20.94,74.53 20.94,74.38 21.05,74.26 21.62,74.26 21.73,74.15 21.73,73.06 21.62,72.95 21.11,72.95 21,72.84 21,72.68 21.11,72.57 21.62,72.57 21.73,72.46 21.73,71.15 21.62,71.04 21.05,71.04 20.94,70.93 20.94,70.77 21.05,70.66 21.62,70.66 21.73,70.55 21.73,67.75 21.62,67.64 21.1,67.64 20.99,67.53 20.99,67.37 21.1,67.26 21.62,67.26 21.73,67.15 21.73,66.99 21.62,66.88 21.1,66.88 20.99,66.77 20.99,66.61 21.1,66.5 21.62,66.5 21.73,66.39 21.73,65.15 29.1,57.78 29.67,57.78 29.67,57.78 30.02,57.78 30.66,57.78 31.39,57.05 34.32,57.05 36.6,54.78 36.6,51.59 36.97,51.22 v1(36.97,50.05)
  LYR4 w0.127: v1(23.57,87.03) 24.02,86.59 25.21,86.59 26.15,85.65 26.15,82.01 25.75,81.61 v1(25.71,81.61)
  BOTTOM w0.121: U26.30 27.46,75.37 27.87,75.78 27.87,77.15 28.13,77.41 28.48,77.41 28.83,77.76 28.83,78.74 27.38,80.19 26.9,80.19 26.3,80.8 26.3,81.06 25.75,81.61 v1(25.71,81.61)
GPMC_AD13: length 101.1
  TOP w0.121: v1(36.97,49.25) U14.R12 ; U1.G5 v1(24.37,87.83)
  LYR3 w0.127: v1(24.59,82.13) 21.92,82.13 19.38,79.58 19.38,76.02 20.1,75.3 20.1,62.26 21.08,61.28 22.2,61.28 22.3,61.39 22.3,61.83 22.42,61.94 22.57,61.94 22.68,61.83 22.68,61.4 22.8,61.28 24.3,61.28 29.32,56.26 31.45,56.26 32.13,55.59 32.13,55.19 32.69,54.63 34.07,54.63 34.67,54.03 35.06,54.03 35.33,53.76 35.33,50.65 35.76,50.21 35.76,49.9 36.01,49.66 36.48,49.66 36.71,49.43 36.79,49.43 v1(36.97,49.25)
  LYR4 w0.127: v1(24.37,87.83) 24.78,87.43 25.57,87.43 26.63,86.36 26.63,81.92 25.9,81.19 25.47,81.19 24.59,82.07 v1(24.59,82.13)
  BOTTOM w0.121: J4.28 11.89,99.46 13.55,99.46 14.79,98.22 14.79,94.07 17,91.86 17,85.75 17.98,84.76 17.99,84.76 18.35,84.4 18.35,84.4 19.14,83.6 19.15,83.6 19.5,83.25 20.76,83.25 21.15,82.86 23.86,82.86 v1(24.59,82.13) 24.59,82.67 24.8,82.87 25.33,82.87 25.43,82.77 25.43,82.53 25.25,82.35 25.25,81.42 26.78,79.89 27.25,79.89 28.5,78.65 28.5,77.85 28.36,77.71 27.75,77.71 27.57,77.53 27.57,75.95 27.37,75.75 25.54,75.75 U26.29
GPMC_AD14: length 99.9
  TOP w0.121: U14.V13 36.57,51.65 36.92,52.01 36.92,53.78 36.46,54.25 36.46,55.01 34.82,56.64 30.43,56.64 30.29,56.5 29.4,56.5 25.15,60.75 25.15,61.62 22.27,64.5 22.27,69.13 21.93,69.48 21.93,69.64 22.41,70.12 22.41,70.27 22.31,70.38 22.16,70.38 21.67,69.89 21.52,69.89 21.42,69.99 21.42,70.14 21.69,70.42 21.69,70.57 21.59,70.68 21.44,70.68 21.16,70.4 21.01,70.4 20.9,70.5 20.9,70.65 21.18,70.93 21.18,71.08 21.08,71.19 20.93,71.19 20.65,70.91 20.5,70.91 20.39,71.02 20.39,71.17 20.67,71.44 20.67,71.59 20.56,71.7 20.41,71.7 20.14,71.42 19.99,71.42 19.88,71.53 19.88,71.68 20.16,71.96 20.16,72.11 20.05,72.21 19.9,72.21 19.62,71.93 19.47,71.93 19.3,72.11 19.3,79.93 20.59,81.23 v1(23.76,81.23) ; U1.F5 v1(23.57,87.83)
  LYR4 w0.127: v1(23.57,87.83) 23.16,87.43 23.16,84.91 22.5,84.25 22.5,82.81 22.62,82.7 23.1,82.7 23.21,82.58 23.21,82.43 23.1,82.32 22.62,82.32 22.5,82.2 22.5,81.4 22.68,81.23 v1(23.76,81.23)
  BOTTOM w0.121: U26.27 26.58,76.57 26.68,76.66 26.68,76.83 26.8,76.95 27.16,76.95 27.27,77.06 27.27,77.72 27.81,78.27 27.81,78.83 27.06,79.58 26.66,79.58 24.72,81.53 24.49,81.53 24.18,81.84 24.18,82.11 23.79,82.5 23.23,82.5 23.07,82.33 23.07,81.96 23.22,81.81 23.61,81.81 23.76,81.67 v1(23.76,81.23) 23.71,81.18 23.58,81.31 23.54,81.31 23.54,81.32 23.24,81.32 22.54,82.01 22.12,82.44 19.8,82.44 17.84,84.4 17.83,84.4 16.53,85.7 16.53,91.39 14.29,93.64 14.29,93.64 13.69,94.23 13.69,94.23 13.33,94.59 13,94.59 12.01,95.59 12.01,95.92 10.64,97.28 10.18,97.28 9.72,97.75 9.72,99.82 J4.30
